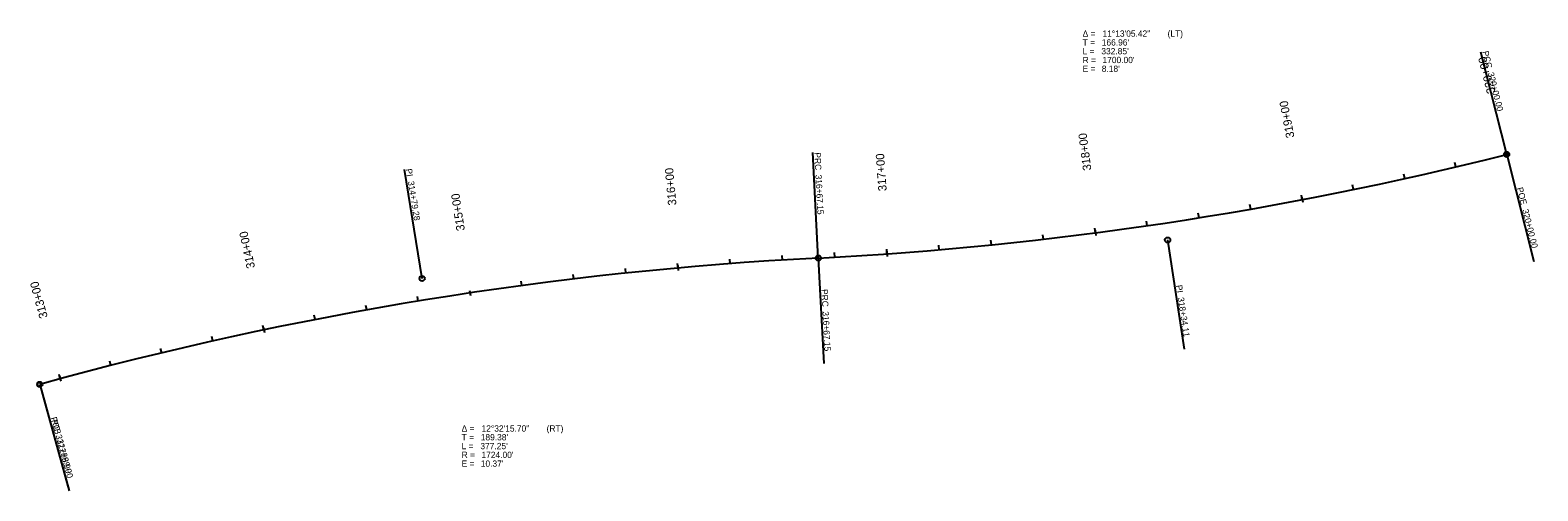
# Model space of a CAD drawing. Extents: x 21446638 to 21447358, y 8416474 to 8416694.
import ezdxf

# ---------------------------------------------------------------- set-up
doc = ezdxf.new("R2010")
doc.units = 0
for name, color, linetype in [('4f', 7, 'Continuous'), ('Alignment', 7, 'Continuous'), ('TextAlignment', 7, 'Continuous'), ('TextAlignmentLrg', 7, 'Continuous'), ('TextAlignmentSml', 7, 'Continuous')]:
    doc.layers.add(name, color=color, linetype=linetype)

msp = doc.modelspace()

# ---------------------------------------------------------------- linework, layer by layer
at = {"layer": '4f'}
msp.add_arc((21446926.73, 8418283.05), 1700, 272.95752, 284.17569, dxfattribs=at)
at = {"layer": 'Alignment'}
for centre, radius, start, end in [((21446926.73, 8418283.05), 1700, 272.95752, 284.17569), ((21447103.39, 8414863.61), 1724, 92.95752, 105.49522)]:
    msp.add_arc(centre, radius, start, end, dxfattribs=at)
at = {"layer": 'TextAlignment'}
for p, q in [((21447343.05, 8416634.82), (21447330.71, 8416683.68)), ((21447330.71, 8416683.68), (21447330.71, 8416683.68)), ((21447014.44, 8416585.31), (21447011.84, 8416635.65)), ((21447011.84, 8416635.65), (21447011.84, 8416635.65)), ((21447343.05, 8416634.82), (21447355.98, 8416583.62)), ((21446825.31, 8416575.54), (21446816.85, 8416627.66)), ((21446816.85, 8416627.66), (21446816.85, 8416627.66)), ((21447181.18, 8416593.93), (21447189.04, 8416541.72)), ((21447014.44, 8416585.31), (21447017.04, 8416534.98)), ((21447355.98, 8416583.62), (21447355.98, 8416583.62)), ((21447189.04, 8416541.72), (21447189.04, 8416541.72)), ((21447017.04, 8416534.98), (21447017.04, 8416534.98)), ((21446642.81, 8416524.95), (21446656.28, 8416476.38)), ((21446642.81, 8416524.95), (21446656.92, 8416474.07)), ((21446656.28, 8416476.38), (21446656.28, 8416476.38)), ((21446656.92, 8416474.07), (21446656.92, 8416474.07))]:
    msp.add_line(p, q, dxfattribs=at)
for centre, radius in [((21447343.05, 8416634.82), 1.25), ((21447343.05, 8416634.82), 1.07), ((21447181.18, 8416593.93), 1.25), ((21447014.44, 8416585.31), 1.25), ((21447014.44, 8416585.31), 1.25), ((21446825.31, 8416575.54), 1.25), ((21446642.81, 8416524.95), 1.25), ((21446642.81, 8416524.95), 1.07)]:
    msp.add_circle(centre, radius, dxfattribs=at)
at = {"layer": 'TextAlignmentLrg'}
for p, q in [((21447342.75, 8416636), (21447343.35, 8416633.63)), ((21447245.43, 8416613.19), (21447245.03, 8416615.34)), ((21447146.71, 8416597.34), (21447146.43, 8416599.51)), ((21447047.23, 8416587.33), (21447047.08, 8416589.5)), ((21446947.47, 8416580.54), (21446947.27, 8416582.72)), ((21446848.01, 8416569.83), (21446848.38, 8416567.41)), ((21446749.78, 8416550.95), (21446749.33, 8416553.09)), ((21446652.56, 8416527.62), (21446651.99, 8416529.73))]:
    msp.add_line(p, q, dxfattribs=at)
at = {"layer": 'TextAlignmentSml'}
for p, q in [((21447318.77, 8416628.87), (21447318.27, 8416631)), ((21447342.75, 8416636), (21447343.35, 8416633.63)), ((21447294.4, 8416623.28), (21447293.93, 8416625.42)), ((21447269.96, 8416618.06), (21447269.51, 8416620.2)), ((21447220.84, 8416608.68), (21447220.47, 8416610.84)), ((21447245.2, 8416614.39), (21447245.66, 8416611.99)), ((21447171.48, 8416600.76), (21447171.16, 8416602.92)), ((21447196.19, 8416604.54), (21447195.84, 8416606.7)), ((21447121.9, 8416594.29), (21447121.65, 8416596.46)), ((21447146.55, 8416598.56), (21447146.87, 8416596.13)), ((21447022.28, 8416585.74), (21447022.16, 8416587.92)), ((21447047.14, 8416588.55), (21447047.32, 8416586.1)), ((21447072.15, 8416589.28), (21447071.97, 8416591.46)), ((21447097.05, 8416591.6), (21447096.83, 8416593.78)), ((21446922.59, 8416578.1), (21446922.36, 8416580.27)), ((21446947.36, 8416581.76), (21446947.58, 8416579.32)), ((21446972.38, 8416582.62), (21446972.21, 8416584.8)), ((21446997.32, 8416584.34), (21446997.19, 8416586.52)), ((21446872.94, 8416572.14), (21446872.65, 8416574.3)), ((21446897.74, 8416575.3), (21446897.48, 8416577.47)), ((21446823.5, 8416564.74), (21446823.14, 8416566.89)), ((21446848.01, 8416569.83), (21446848.38, 8416567.41)), ((21446798.86, 8416560.5), (21446798.47, 8416562.65)), ((21446749.53, 8416552.15), (21446750.03, 8416549.76)), ((21446774.29, 8416555.91), (21446773.87, 8416558.05)), ((21446725.35, 8416545.65), (21446724.87, 8416547.78)), ((21446701, 8416539.99), (21446700.49, 8416542.11)), ((21446676.73, 8416533.98), (21446676.19, 8416536.1)), ((21446652.24, 8416528.8), (21446652.88, 8416526.44))]:
    msp.add_line(p, q, dxfattribs=at)

# ---------------------------------------------------------------- texts
at = {"layer": 'TextAlignment'}
for s, p in [('T = ', (21447140.62, 8416686.83)), ('Δ = ', (21447140.62, 8416691.03)), ("166.96'", (21447149.75, 8416686.83)), ('11°13\'05.42"', (21447150.12, 8416691.03)), (' (LT)', (21447180.06, 8416691.03)), ('L = ', (21447140.62, 8416682.63)), ('R = ', (21447140.62, 8416678.43)), ("332.85'", (21447149.56, 8416682.63)), ("1700.00'", (21447150.11, 8416678.43)), ('E = ', (21447140.62, 8416674.23)), ("8.18'", (21447149.75, 8416674.23)), ('T = ', (21446844.19, 8416498.18)), ('Δ = ', (21446844.19, 8416502.38)), ("189.38'", (21446853.31, 8416498.18)), ('12°32\'15.70"', (21446853.69, 8416502.38)), (' (RT)', (21446883.63, 8416502.38)), ('L = ', (21446844.19, 8416493.98)), ("377.25'", (21446853.13, 8416493.98)), ('R = ', (21446844.19, 8416489.78)), ('E = ', (21446844.19, 8416485.58)), ("10.37'", (21446853.32, 8416485.58)), ("1724.00'", (21446853.67, 8416489.78))]:
    msp.add_text(s, height=3, dxfattribs=at).set_placement(p)
for s, rotation, p in [('PCC', 284.17569, (21447331.35, 8416683.84)), ('320+00.00', 284.17569, (21447333.92, 8416673.67)), ('PRC', 272.95752, (21447012.5, 8416635.68)), ('PI ', 279.22637, (21446817.5, 8416627.76)), ('316+67.15', 272.95752, (21447013.05, 8416625.06)), ('314+79.28', 279.22637, (21446818.46, 8416621.86)), ('POE ', 284.17569, (21447347.81, 8416618.69)), ('320+00.00', 284.17569, (21447350.44, 8416608.26)), ('PRC', 272.95752, (21447015.87, 8416570.38)), ('PI ', 278.56661, (21447185.11, 8416572.23)), ('318+34.11', 278.56661, (21447186, 8416566.32)), ('316+67.15', 272.95752, (21447016.42, 8416559.76)), ('POB ', 285.49522, (21446647.94, 8416508.93)), ('PC', 285.49522, (21446648.27, 8416507.71)), ('312+89.90', 285.49522, (21446650.27, 8416500.52)), ('312+89.90', 285.49522, (21446650.9, 8416498.25))]:
    msp.add_text(s, height=3, rotation=rotation, dxfattribs=at).set_placement(p)
at = {"layer": 'TextAlignmentLrg'}
for s, rotation, p in [('320+00', 104.17569, (21447337.65, 8416664.39)), ('315+00', 98.51262, (21446845.74, 8416598.58))]:
    msp.add_text(s, height=4.008, rotation=rotation, dxfattribs=at).set_placement(p)
at = {"layer": 'TextAlignmentSml'}
for s, rotation, p in [('320+00', 104.17569, (21447337.65, 8416664.39)), ('319+00', 100.80535, (21447241.78, 8416643.03)), ('318+00', 97.43501, (21447144.82, 8416627.35)), ('317+00', 94.06467, (21447047.1, 8416617.39)), ('316+00', 95.1892, (21446946.75, 8416610.6)), ('315+00', 98.51262, (21446845.74, 8416598.58)), ('314+00', 101.83604, (21446745.59, 8416580.73)), ('313+00', 105.15947, (21446646.65, 8416557.1))]:
    msp.add_text(s, height=4.008, rotation=rotation, dxfattribs=at).set_placement(p)

doc.saveas('drawing.dxf')
